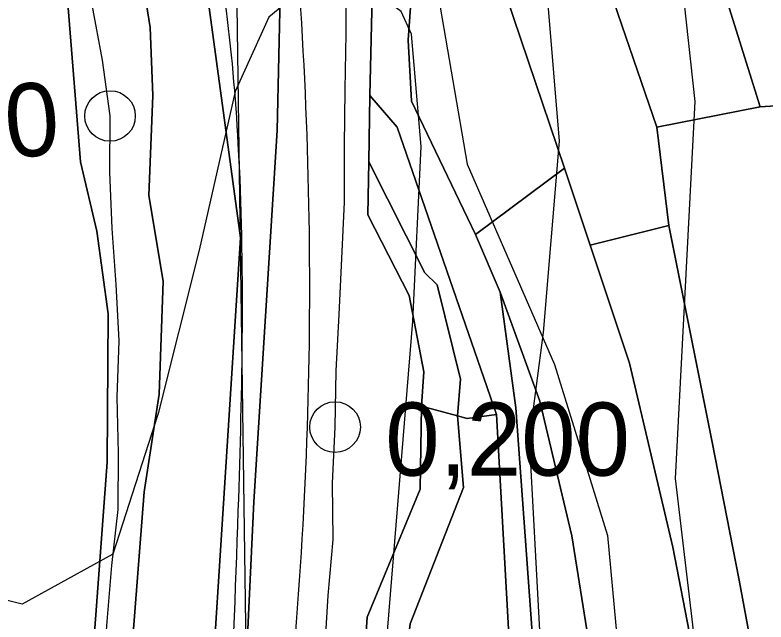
# Model space of a CAD drawing. Extents: x -510989 to -501240, y -1184665 to -1176089.
# Drawn here: x -503157.8 to -503024.3, y -1182404.5 to -1182296.6 of the extents above; entities that cross this region are included whole.
import ezdxf

# ---------------------------------------------------------------- set-up
doc = ezdxf.new("R2010")
doc.units = 0
for name, color, linetype in [('lesni_pozemek', 7, 'Continuous'), ('NAVRH_revitalizace_toku', 7, 'Continuous'), ('orna_puda', 7, 'Continuous'), ('ostatni_plocha_x_draha', 7, 'Continuous'), ('ostatni_plocha_x_neplodna_puda', 7, 'Continuous'), ('ostatni_plocha_x_ostatni_komunikace', 7, 'Continuous'), ('STAV_systematicke_odvodneni', 7, 'Continuous'), ('STAV_zaplavove_uzemi', 7, 'Continuous'), ('trasovani_toku', 7, 'Continuous'), ('trvaly_travni_porost', 7, 'Continuous'), ('vodni_plocha_x_vodni_tok_v_koryt_prir_n_upr', 7, 'Continuous'), ('vrstevnice_01', 7, 'Continuous'), ('vrstevnice_02', 7, 'Continuous')]:
    doc.layers.add(name, color=color, linetype=linetype)

msp = doc.modelspace()

# ---------------------------------------------------------------- linework, layer by layer
at = {"layer": 'lesni_pozemek'}
for points in [[(-503079.15, -1182367.84), (-503078.09, -1182380.56), (-503087.58, -1182404.79), (-503091.71, -1182440.52), (-503098.97, -1182462.87), (-503096.76, -1182426.68), (-503095.23, -1182403.6), (-503085.8, -1182380.85), (-503085.56, -1182366.14)], [(-503072.22, -1182367.61), (-503067.84, -1182445.9), (-503097.87, -1182466.35), (-503098.97, -1182462.87), (-503091.71, -1182440.52), (-503087.58, -1182404.79), (-503078.09, -1182380.56), (-503079.15, -1182367.84), (-503077.44, -1182368.29)]]:
    msp.add_lwpolyline(points, close=True, dxfattribs=at)
at = {"layer": 'NAVRH_revitalizace_toku'}
msp.add_lwpolyline([(-503133.77, -1182580.05), (-503116.33, -1182438.8), (-503118.35, -1182295.01), (-503137.16, -1182224.46), (-503172.77, -1182139.13), (-503205.02, -1182088.74), (-503270.19, -1182028.27)], dxfattribs=at)
at = {"layer": 'orna_puda'}
for points in [[(-503054.55, -1182233.14), (-503041.42, -1182233.1), (-503029.33, -1182237.73), (-503022.21, -1182259.94), (-503015.73, -1182282.44), (-503012.62, -1182312.1), (-503025.38, -1182312.91), (-503038.77, -1182270.09), (-503045.82, -1182248.64)], [(-503057.58, -1182276.05), (-503038.77, -1182270.09), (-503025.38, -1182312.91), (-503043.73, -1182316.51)]]:
    msp.add_lwpolyline(points, close=True, dxfattribs=at)
at = {"layer": 'ostatni_plocha_x_draha'}
for points in [[(-503126.54, -1182683.63), (-503129.17, -1182627.68), (-503126.88, -1182554.23), (-503123.3, -1182528.2), (-503119.99, -1182481.15), (-503115.36, -1182383.12), (-503111.24, -1182317.1), (-503110.3, -1182277.24), (-503109.8, -1182255.85), (-503111.53, -1182238.57), (-503112.06, -1182233.36), (-503112.99, -1182224.03), (-503138.92, -1182149.41)], [(-503088.5, -1182181.63), (-503082, -1182219.91), (-503085.32, -1182237.31), (-503093.79, -1182270.83), (-503094.74, -1182310.88), (-503094.9, -1182322.7), (-503095.11, -1182332.11), (-503087.76, -1182346.48), (-503085.13, -1182360.01), (-503085.56, -1182366.14), (-503085.8, -1182380.85), (-503095.23, -1182403.6), (-503096.76, -1182426.68)]]:
    msp.add_lwpolyline(points, dxfattribs=at)
at = {"layer": 'ostatni_plocha_x_neplodna_puda'}
msp.add_lwpolyline([(-503071.57, -1182345.84), (-503064.53, -1182365.23), (-503058.81, -1182389.15), (-503053.98, -1182419.59), (-503051.42, -1182453.18), (-503046.92, -1182471.93), (-503028.69, -1182475.02), (-503018.89, -1182476.69), (-503018.19, -1182481.05), (-503008.98, -1182480.59), (-503012.21, -1182494.1), (-502994.52, -1182510.67), (-502987.16, -1182537.51), (-503056.55, -1182535.08), (-503068.78, -1182366.4)], close=True, dxfattribs=at)
at = {"layer": 'ostatni_plocha_x_ostatni_komunikace'}
for points in [[(-503080.26, -1182177.3), (-503068.33, -1182216.62), (-503066.86, -1182227.28), (-503067.74, -1182229.16), (-503070.75, -1182235.59), (-503072.69, -1182238.24), (-503075.36, -1182241.63), (-503083.22, -1182264.69), (-503085.9, -1182272.55), (-503087.92, -1182301.08), (-503087.32, -1182311.93), (-503075.95, -1182335.6), (-503071.57, -1182345.84), (-503068.78, -1182366.4), (-503056.55, -1182535.08)], [(-503071.56, -1182668.66), (-503069.66, -1182654.63), (-503065.08, -1182639.64), (-503059.66, -1182619.78), (-503058.21, -1182607.17), (-503058.73, -1182597.26), (-503060.91, -1182587.75), (-503060.03, -1182576.61), (-503058.76, -1182566.53), (-503059.25, -1182557.54), (-503059.9, -1182547.05), (-503060.31, -1182539.99), (-503060.77, -1182534.41), (-503061.35, -1182523.03), (-503065.41, -1182494.92), (-503067.05, -1182467.78), (-503067.84, -1182445.9), (-503072.22, -1182367.61), (-503089.91, -1182316.52), (-503094.74, -1182310.88), (-503093.79, -1182270.83), (-503085.32, -1182237.31), (-503082, -1182219.91), (-503088.5, -1182181.63)], [(-503141.33, -1182199.87), (-503127.48, -1182238.47), (-503124.91, -1182246.01), (-503123.6, -1182251.03), (-503118.37, -1182260.09), (-503110.3, -1182277.24), (-503111.24, -1182317.1), (-503115.36, -1182383.12), (-503119.99, -1182481.15), (-503123.3, -1182528.2), (-503126.88, -1182554.23), (-503129.17, -1182627.68), (-503126.54, -1182683.63)], [(-503130.43, -1182670.57), (-503131.22, -1182658.04), (-503131.94, -1182644.64), (-503132.71, -1182630.17), (-503131.56, -1182616.1), (-503131.29, -1182604.26), (-503131.1, -1182594.1), (-503130.92, -1182583.43), (-503130.44, -1182571.46), (-503136.2, -1182556.7), (-503133.11, -1182531.89), (-503132.72, -1182528.5), (-503130.83, -1182514.34), (-503125.98, -1182464.86), (-503117.74, -1182336.23), (-503123.39, -1182294.84), (-503133.1, -1182250.65), (-503146.06, -1182212.7)]]:
    msp.add_lwpolyline(points, dxfattribs=at)
at = {"layer": 'STAV_systematicke_odvodneni'}
for p, q in [((-503083.22, -1182289.65), (-503077.44, -1182323.11)), ((-503077.44, -1182323.11), (-503061.94, -1182358.69)), ((-503061.94, -1182358.69), (-503052.51, -1182389.1)), ((-503052.51, -1182389.1), (-503047.35, -1182445.06))]:
    msp.add_line(p, q, dxfattribs=at)
at = {"layer": 'STAV_zaplavove_uzemi'}
for points in [[(-502723.47, -1180576.88), (-502750.97, -1180610.73), (-502772.12, -1180647.75), (-502783.76, -1180692.17), (-502790.11, -1180735.54), (-502816.55, -1180769.39), (-502838.76, -1180789.49), (-502880.02, -1180813.82), (-502947.71, -1180825.45), (-502980.5, -1180833.91), (-503008.01, -1180838.14), (-503027.04, -1180827.57), (-503058.78, -1180840.26), (-503097.92, -1180865.65), (-503133.88, -1180877.28), (-503224.85, -1180888.92), (-503331.68, -1180909.01), (-503349.66, -1180914.3), (-503380.34, -1180944.98), (-503395.15, -1180996.81), (-503404.67, -1181054.99), (-503414.18, -1181088.83), (-503405.74, -1181137.71), (-503341.21, -1181192.71), (-503275.63, -1181213.86), (-503238.61, -1181228.67), (-503221.69, -1181245.6), (-503229.09, -1181273.1), (-503244.96, -1181310.12), (-503251.3, -1181333.39), (-503243.9, -1181363.01), (-503246.02, -1181393.68), (-503244.96, -1181433.88), (-503251.3, -1181477.25), (-503261.88, -1181518.5), (-503269.29, -1181530.14), (-503299, -1181579.21), (-503326.93, -1181610.62), (-503351.36, -1181638.55), (-503381.61, -1181666.47), (-503397.91, -1181682.76), (-503420.01, -1181721.16), (-503428.16, -1181736.28), (-503464.23, -1181735.12), (-503497.97, -1181758.39), (-503482.84, -1181800.28), (-503460.74, -1181841), (-503407.53, -1181883.86), (-503369.52, -1181914.83), (-503348.4, -1181945.81), (-503334.32, -1181976.78), (-503286.45, -1182017.61), (-503224.5, -1182073.92), (-503185.08, -1182121.79), (-503159.74, -1182180.92), (-503125.16, -1182269.48), (-503118.18, -1182319.52), (-503118.18, -1182384.67), (-503122.84, -1182470.78), (-503133.31, -1182562.7), (-503147.27, -1182666.25), (-503152.24, -1182800.82), (-503140.98, -1182878.25), (-503110, -1182947.24), (-503050.82, -1183014.1), (-502950.75, -1183132.78), (-502862.33, -1183242.16), (-502789.02, -1183301.5), (-502594.33, -1183372.67), (-502552.52, -1183394.35), (-502521.54, -1183433.06), (-502481.28, -1183546.12), (-502442.56, -1183663.81), (-502399.2, -1183755.19), (-502318.67, -1183838.81), (-502270.66, -1183889.92), (-502173.29, -1183977.22)], [(-502250.32, -1184002.61), (-502355.07, -1183875.41), (-502442.37, -1183790.61), (-502477.29, -1183700.82), (-502532.16, -1183578.61), (-502567.08, -1183448.91), (-502626.05, -1183402.34), (-502705.41, -1183380.59), (-502814.2, -1183349.87), (-502882.03, -1183297.39), (-502931.95, -1183237.24), (-503042.02, -1183107.97), (-503139.64, -1183018.94), (-503222.14, -1182957.59), (-503308.56, -1182839.96), (-503316.24, -1182784.92), (-503330.32, -1182756.77), (-503348.24, -1182719.65), (-503334.16, -1182651.82), (-503323.92, -1182595.5), (-503313.68, -1182526.39), (-503294.1, -1182480.5), (-503251.86, -1182396.03), (-503229.34, -1182314.37), (-503216.1, -1182227.15), (-503242.43, -1182174.5), (-503271.86, -1182129.59), (-503287.34, -1182081.58), (-503343.88, -1182028.1), (-503361.79, -1182008.91), (-503396.35, -1181952.59), (-503442.43, -1181933.39), (-503497.46, -1181888.6), (-503525.62, -1181860.44), (-503528.18, -1181837.4), (-503548.66, -1181767.01), (-503558.9, -1181729.89), (-503576.82, -1181682.53), (-503578.1, -1181621.1), (-503567.86, -1181572.46), (-503552.5, -1181536.63), (-503538.04, -1181458.36), (-503518.33, -1181411.9), (-503509.88, -1181341.51), (-503497.21, -1181207.63), (-503499.77, -1181097.56), (-503498.02, -1181031.35), (-503510.82, -1180970.85), (-503549.22, -1180952.23), (-503571.32, -1180940.6), (-503605.07, -1180937.11), (-503651.61, -1180939.44), (-503671.39, -1180917.33), (-503679.53, -1180892.89), (-503713.27, -1180871.95), (-503727.24, -1180859.15), (-503734.22, -1180833.55), (-503728.4, -1180799.81), (-503741.2, -1180770.72), (-503722.82, -1180725.17), (-503721.54, -1180703.41), (-503731.78, -1180697.01), (-503767.61, -1180699.57), (-503790.65, -1180697.01), (-503817.53, -1180697.01), (-503861.04, -1180686.77), (-503889.2, -1180675.25), (-503900.72, -1180668.85), (-503953.2, -1180679.09), (-503997.99, -1180697.01), (-504063.27, -1180722.61), (-504109.34, -1180749.49), (-504142.62, -1180776.36), (-504177.18, -1180796.84), (-504211.73, -1180817.32), (-504414.98, -1180961.5), (-504472.7, -1180998.11), (-504544.51, -1181068.5), (-504600.82, -1181143.12), (-504621.94, -1181196.62), (-504641.65, -1181267.01), (-504660.25, -1181350.62), (-504634.7, -1181398.32), (-504617.66, -1181447.72), (-504600.62, -1181492.01), (-504587, -1181548.23), (-504592.11, -1181628.29), (-504569.96, -1181682.81), (-504568.26, -1181664.07), (-504554.63, -1181621.48), (-504547.82, -1181597.63)], [(-502765.18, -1180820.83), (-502819.12, -1180854.68), (-502855.09, -1180856.79), (-502878.36, -1180851.5), (-502911.15, -1180848.33), (-502954.52, -1180870.54), (-502984.14, -1180869.48), (-503005.29, -1180861.02), (-503048.66, -1180872.66), (-503074.04, -1180895.93), (-503100.49, -1180910.74), (-503124.82, -1180934.01), (-503148.09, -1180961.51), (-503167.13, -1180991.13), (-503214.18, -1181039.04), (-503223.14, -1181058.24), (-503224.42, -1181086.39), (-503233.38, -1181129.91), (-503224.42, -1181152.95), (-503210.34, -1181174.71), (-503189.86, -1181187.51), (-503177.06, -1181216.94), (-503187.3, -1181265.58), (-503182.09, -1181326.92), (-503202.22, -1181367.18), (-503223.9, -1181396.6), (-503227, -1181422.93), (-503244.04, -1181475.59), (-503248.68, -1181509.66), (-503278.16, -1181558.16), (-503308.83, -1181601.52), (-503351.14, -1181645.95), (-503365.95, -1181659.7), (-503395.57, -1181685.09), (-503411.43, -1181722.11), (-503422.01, -1181739.03), (-503437.88, -1181747.49), (-503460.09, -1181743.26), (-503481.25, -1181748.55), (-503492.88, -1181761.25), (-503472.79, -1181803.56), (-503443.17, -1181840.58), (-503413.55, -1181857.5), (-503278.84, -1181941.97), (-503242.23, -1181977.17), (-503180.29, -1182027.85), (-503125.38, -1182098.25), (-503088.78, -1182167.23), (-503075.54, -1182217), (-503114.26, -1182162.8), (-503152.97, -1182091.56), (-503197.89, -1182048.2), (-503210.28, -1182032.71), (-503231.96, -1182021.87), (-503259.83, -1182017.22), (-503266.03, -1182021.87), (-503224.21, -1182048.2), (-503199.43, -1182076.07), (-503157.62, -1182114.79), (-503135.94, -1182159.7), (-503118.9, -1182207.71), (-503111.16, -1182251.07), (-503108.24, -1182409.43), (-503115.92, -1182478.55), (-503128.72, -1182603.98), (-503131.28, -1182696.13), (-503104.4, -1182780.6), (-503071.45, -1182869.91), (-503052.71, -1182886.94), (-502977.76, -1182944.86), (-502838.07, -1183047.07), (-502664.31, -1183174.84), (-502563.8, -1183270.24), (-502485.44, -1183353.71), (-502446.26, -1183432.07), (-502383.48, -1183571.46), (-502315.46, -1183658.04), (-502253.62, -1183724), (-502158.8, -1183808.51), (-502045.43, -1183923.94), (-501930, -1184016.7), (-501793.89, -1184089.91), (-501746.5, -1184127.32), (-501709.09, -1184197.15)], [(-502226.81, -1183999.33), (-502311.75, -1183908.57), (-502419.96, -1183792.22), (-502451.37, -1183739.86), (-502483.95, -1183647.94), (-502521.19, -1183547.88), (-502550.27, -1183461.78), (-502572.38, -1183429.2), (-502656.85, -1183386.44), (-502768.21, -1183357), (-502834.76, -1183325), (-502889.79, -1183272.53), (-502938.43, -1183213.65), (-503042.23, -1183094.94), (-503121.07, -1183000.61), (-503188.65, -1182909.1), (-503198.5, -1182830.26), (-503192.9, -1182654.04), (-503169.63, -1182457.41), (-503165.02, -1182331.94), (-503174.64, -1182244.43), (-503211.18, -1182165.58), (-503248.68, -1182104.04), (-503298.6, -1182058.14), (-503358.04, -1182010.06), (-503388.64, -1181959.36), (-503422.73, -1181920.9), (-503472.56, -1181875.44), (-503525.05, -1181800.26), (-503528.23, -1181753.72), (-503520.82, -1181644.77), (-503514.48, -1181592.94), (-503470.14, -1181471.68), (-503458.61, -1181430.33), (-503465.34, -1181377.45), (-503493.67, -1181297.01), (-503493.67, -1181272.57), (-503489.02, -1181233.01), (-503455.28, -1181146.91), (-503458.77, -1181102.69), (-503461.1, -1181050.33), (-503461.1, -1181016.59), (-503465.75, -1180995.65), (-503478.55, -1180979.36)]]:
    msp.add_spline(points, degree=3, dxfattribs=at)
at = {"layer": 'trasovani_toku'}
for p, q in [((-503098.98, -1182299.87), (-503098.96, -1182289.87)), ((-503142.28, -1182304.64), (-503144.11, -1182294.81)), ((-503099.1, -1182309.87), (-503098.98, -1182299.87)), ((-503140.93, -1182314.55), (-503142.28, -1182304.64)), ((-503099.22, -1182319.87), (-503099.1, -1182309.87)), ((-503140.99, -1182324.55), (-503140.93, -1182314.55)), ((-503099.25, -1182329.87), (-503099.22, -1182319.87)), ((-503140.55, -1182334.54), (-503140.99, -1182324.55)), ((-503099.72, -1182339.85), (-503099.25, -1182329.87)), ((-503139.85, -1182344.51), (-503140.55, -1182334.54)), ((-503100.21, -1182349.84), (-503099.72, -1182339.85)), ((-503139.33, -1182354.5), (-503139.85, -1182344.51)), ((-503100.72, -1182359.83), (-503100.21, -1182349.84)), ((-503139.68, -1182364.49), (-503139.33, -1182354.5)), ((-503100.92, -1182369.83), (-503100.72, -1182359.83)), ((-503139.43, -1182374.49), (-503139.68, -1182364.49)), ((-503101.36, -1182379.82), (-503100.92, -1182369.83)), ((-503139.5, -1182384.49), (-503139.43, -1182374.49)), ((-503101.28, -1182389.82), (-503101.36, -1182379.82)), ((-503140.6, -1182394.43), (-503139.5, -1182384.49)), ((-503102.18, -1182399.78), (-503101.28, -1182389.82)), ((-503141.44, -1182404.39), (-503140.6, -1182394.43)), ((-503102.76, -1182409.76), (-503102.18, -1182399.78)), ((-503142.09, -1182414.37), (-503141.44, -1182404.39))]:
    msp.add_line(p, q, dxfattribs=at)
for centre in [(-503140.93, -1182314.55), (-503100.92, -1182369.83)]:
    msp.add_circle(centre, 4.5, dxfattribs=at)
at = {"layer": 'trvaly_travni_porost'}
for points in [[(-503083.22, -1182264.69), (-503075.36, -1182241.63), (-503080.69, -1182271.17), (-503083.13, -1182284.72), (-503076.31, -1182282.41), (-503074.35, -1182281.74), (-503060.16, -1182323.83), (-503075.95, -1182335.6), (-503087.32, -1182311.93), (-503087.92, -1182301.08), (-503085.9, -1182272.55)], [(-503060.97, -1182277.2), (-503057.58, -1182276.05), (-503043.73, -1182316.51), (-503041.59, -1182334.02), (-503055.56, -1182337.5), (-503060.16, -1182323.83), (-503074.35, -1182281.74), (-503071.21, -1182280.67)], [(-503089.91, -1182316.52), (-503072.22, -1182367.61), (-503077.44, -1182368.29), (-503079.15, -1182367.84), (-503078.62, -1182361.34), (-503082.79, -1182344.53), (-503084.97, -1182342.42), (-503094.9, -1182322.7), (-503094.74, -1182310.88)], [(-503012.62, -1182312.1), (-503007.8, -1182362.37), (-503005.59, -1182377.01), (-503001.46, -1182408.98), (-502998.7, -1182436.92), (-503022.03, -1182436.3), (-503022.42, -1182433.2), (-503029.06, -1182397.04), (-503033.96, -1182372.25), (-503041.59, -1182334.02), (-503043.73, -1182316.51), (-503025.38, -1182312.91)], [(-503075.95, -1182335.6), (-503060.16, -1182323.83), (-503055.56, -1182337.5), (-503048.57, -1182358.46), (-503040.91, -1182391.16), (-503034.38, -1182424.85), (-503030.35, -1182451.87), (-503028.69, -1182475.02), (-503046.92, -1182471.93), (-503051.42, -1182453.18), (-503053.98, -1182419.59), (-503058.81, -1182389.15), (-503064.53, -1182365.23), (-503071.57, -1182345.84)], [(-503055.56, -1182337.5), (-503041.59, -1182334.02), (-503033.96, -1182372.25), (-503029.06, -1182397.04), (-503022.42, -1182433.2), (-503022.03, -1182436.3), (-503018.89, -1182476.69), (-503028.69, -1182475.02), (-503030.35, -1182451.87), (-503034.38, -1182424.85), (-503040.91, -1182391.16), (-503048.57, -1182358.46)]]:
    msp.add_lwpolyline(points, close=True, dxfattribs=at)
at = {"layer": 'vodni_plocha_x_vodni_tok_v_koryt_prir_n_upr'}
for points in [[(-503169.21, -1182182.46), (-503153.76, -1182214.14), (-503144.75, -1182242.61), (-503139.92, -1182260.61), (-503133.82, -1182298.85), (-503133.34, -1182310.88), (-503134.04, -1182328.67), (-503131.46, -1182343.93), (-503132.19, -1182363.98), (-503134.87, -1182381.32), (-503138.91, -1182433.1), (-503142.72, -1182460.74), (-503154.71, -1182572.38), (-503160.5, -1182631.31)], [(-503160.5, -1182631.31), (-503154.71, -1182572.38), (-503142.72, -1182460.74), (-503138.91, -1182433.1), (-503134.87, -1182381.32), (-503132.19, -1182363.98), (-503131.46, -1182343.93), (-503134.04, -1182328.67), (-503133.34, -1182310.88), (-503133.82, -1182298.85), (-503139.92, -1182260.61), (-503144.75, -1182242.61), (-503153.76, -1182214.14), (-503169.21, -1182182.46)], [(-503146.06, -1182212.7), (-503133.1, -1182250.65), (-503123.39, -1182294.84), (-503117.74, -1182336.23), (-503125.98, -1182464.86), (-503130.83, -1182514.34), (-503132.72, -1182528.5), (-503133.11, -1182531.89), (-503136.2, -1182556.7), (-503138.46, -1182576.34), (-503140, -1182589.83), (-503141.33, -1182601.44), (-503142.54, -1182612), (-503144.14, -1182625.92), (-503145.9, -1182641.29), (-503147.87, -1182658.56), (-503149.5, -1182672.75)], [(-503162.9, -1182578.73), (-503146.43, -1182443.1), (-503141.44, -1182376.1), (-503141.28, -1182349.69), (-503143.29, -1182335.03), (-503146.18, -1182322.67), (-503148.37, -1182295.34), (-503158.38, -1182222.3)], [(-503158.38, -1182222.3), (-503148.37, -1182295.34), (-503146.18, -1182322.67), (-503143.29, -1182335.03), (-503141.28, -1182349.69), (-503141.44, -1182376.1), (-503146.43, -1182443.1), (-503162.9, -1182578.73)]]:
    msp.add_lwpolyline(points, dxfattribs=at)
msp.add_lwpolyline([(-503094.9, -1182322.7), (-503084.97, -1182342.42), (-503082.79, -1182344.53), (-503078.62, -1182361.34), (-503079.15, -1182367.84), (-503085.56, -1182366.14), (-503085.13, -1182360.01), (-503087.76, -1182346.48), (-503095.11, -1182332.11)], close=True, dxfattribs=at)
at = {"layer": 'vrstevnice_01'}
for points in [[(-503038.81, -1182683), (-503041.91, -1182656), (-503044, -1182610), (-503044.91, -1182607), (-503044.91, -1182551), (-503040.19, -1182523), (-503033.5, -1182470), (-503033.19, -1182451), (-503034.5, -1182429), (-503040.41, -1182379), (-503036.91, -1182312), (-503043.81, -1182249), (-503039.41, -1182240), (-503034.31, -1182237), (-503003, -1182228), (-502990.31, -1182222), (-502982.91, -1182215), (-502982.91, -1182212)], [(-503092.41, -1182727), (-503096.81, -1182709), (-503111.81, -1182664), (-503118, -1182638), (-503118.09, -1182624), (-503115.69, -1182614), (-503103.41, -1182588), (-503096.91, -1182564), (-503095.19, -1182543), (-503096.91, -1182506), (-503095.5, -1182454), (-503087.09, -1182351), (-503085.59, -1182320), (-503087.31, -1182300), (-503089.19, -1182296), (-503097.31, -1182290), (-503100.41, -1182290), (-503106.69, -1182292), (-503112.69, -1182297)], [(-503112.69, -1182297), (-503118.66, -1182310.18), (-503125.1, -1182338.41), (-503132.35, -1182367.45), (-503140.41, -1182392.45), (-503156.52, -1182401.32), (-503169.41, -1182398.1), (-503186.33, -1182377.13), (-503198.53, -1182368.4)]]:
    msp.add_lwpolyline(points, dxfattribs=at)
at = {"layer": 'vrstevnice_02'}
msp.add_lwpolyline([(-503059.41, -1182209), (-503038.19, -1182214), (-503032.59, -1182217), (-503029.81, -1182223), (-503036.09, -1182225), (-503051.5, -1182227), (-503063.19, -1182230), (-503070, -1182236), (-503074.81, -1182243), (-503072.19, -1182260), (-503063.19, -1182294), (-503061.09, -1182319), (-503063.91, -1182353), (-503066.41, -1182372), (-503064.59, -1182406), (-503058.19, -1182446), (-503057, -1182460), (-503060.69, -1182513), (-503060.09, -1182528), (-503062.09, -1182559), (-503066.81, -1182596), (-503077.09, -1182646), (-503079.31, -1182676)], dxfattribs=at)

# ---------------------------------------------------------------- texts
at = {"layer": 'trasovani_toku'}
msp.add_text('2,100', height=13, rotation=4.0873, dxfattribs=at).set_placement((-503192.96, -1182324.44))
msp.add_text('0,200', height=13, dxfattribs=at).set_placement((-503092, -1182378.47))

doc.saveas('drawing.dxf')
